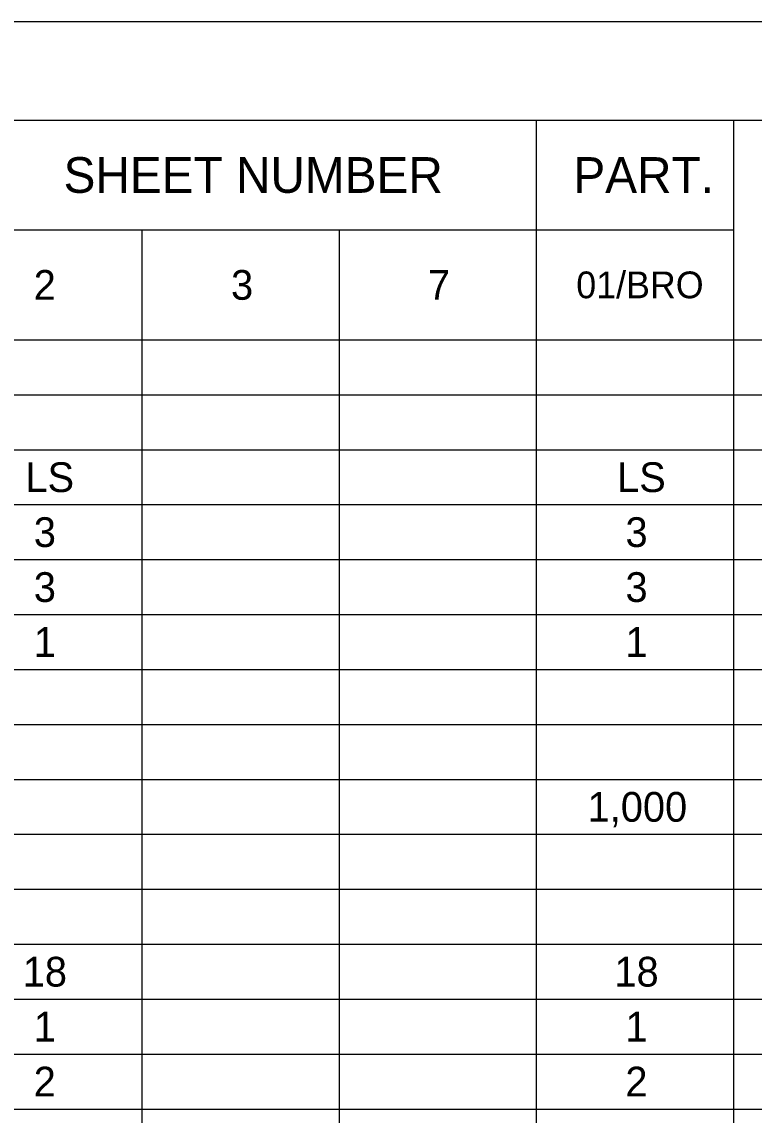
# Model space of a CAD drawing. Extents: x 0 to 34, y 0 to 22.
# Drawn here: x 1.89 to 5.62, y 16.43 to 22 of the extents above; entities that cross this region are included whole.
import ezdxf

# ---------------------------------------------------------------- set-up
doc = ezdxf.new("R2010")
doc.units = 0
for name, color, linetype in [('SH_Border', 7, 'Continuous'), ('SH_Cut_Line', 7, 'Continuous'), ('SH_Text', 7, 'Continuous')]:
    doc.layers.add(name, color=color, linetype=linetype)

msp = doc.modelspace()

# ---------------------------------------------------------------- linework, layer by layer
at = {"layer": 'SH_Border'}
msp.add_lwpolyline([(1.5, 21.5), (33.5, 21.5), (33.5, 0.5), (1.5, 0.5)], close=True, dxfattribs=at)
at = {"layer": 'SH_Cut_Line'}
msp.add_lwpolyline([(0, 0), (34, 0), (34, 22), (0, 22)], close=True, dxfattribs=at)
at = {"layer": 'SH_Text'}
for p, q in [((1.5, 21.5), (32, 21.5)), ((4.5121, 21.5), (4.5121, 0.5138)), ((5.5162, 21.5), (5.5162, 0.5138)), ((1.5, 20.9404), (5.5162, 20.9404)), ((2.504, 20.9404), (2.504, 0.5138)), ((3.5081, 20.9404), (3.5081, 0.5138)), ((1.5, 20.3807), (32, 20.3807)), ((1.5, 20.1009), (32, 20.1009)), ((1.5, 19.8211), (32, 19.8211)), ((1.5, 19.5413), (32, 19.5413)), ((1.5, 19.2615), (32, 19.2615)), ((1.5, 18.9817), (32, 18.9817)), ((1.5, 18.7018), (32, 18.7018)), ((1.5, 18.422), (32, 18.422)), ((1.5, 18.1422), (32, 18.1422)), ((1.5, 17.8624), (32, 17.8624)), ((1.5, 17.5826), (32, 17.5826)), ((1.5, 17.3028), (32, 17.3028)), ((1.5, 17.0229), (32, 17.0229)), ((1.5, 16.7431), (32, 16.7431)), ((1.5, 16.4633), (32, 16.4633))]:
    msp.add_line(p, q, dxfattribs=at)

# ---------------------------------------------------------------- texts
for s, height, p in [('SHEET NUMBER', 0.181716, (2.1056, 21.1293)), ('PART.', 0.18172, (4.7009, 21.1293)), ('2', 0.1514, (1.9536, 20.5848)), ('3', 0.1514, (2.9582, 20.5848)), ('7', 0.1514, (3.9607, 20.5848)), ('01/BRO', 0.13629, (4.7156, 20.5924)), ('LS', 0.15143, (1.9115, 19.6055)), ('LS', 0.15143, (4.9236, 19.6055)), ('3', 0.1514, (1.9542, 19.3257)), ('3', 0.1514, (4.9663, 19.3257)), ('3', 0.1514, (1.9542, 19.0458)), ('3', 0.1514, (4.9663, 19.0458)), ('1', 0.1514, (1.9535, 18.766)), ('1', 0.1514, (4.9656, 18.766)), ('1,000', 0.15143, (4.7735, 17.9266)), ('18', 0.15143, (1.8977, 17.0871)), ('18', 0.15143, (4.9098, 17.0871)), ('1', 0.1514, (1.9535, 16.8073)), ('1', 0.1514, (4.9656, 16.8073)), ('2', 0.1514, (1.9536, 16.5275)), ('2', 0.1514, (4.9657, 16.5275))]:
    msp.add_text(s, height=height, dxfattribs=at).set_placement(p)

doc.saveas('drawing.dxf')
